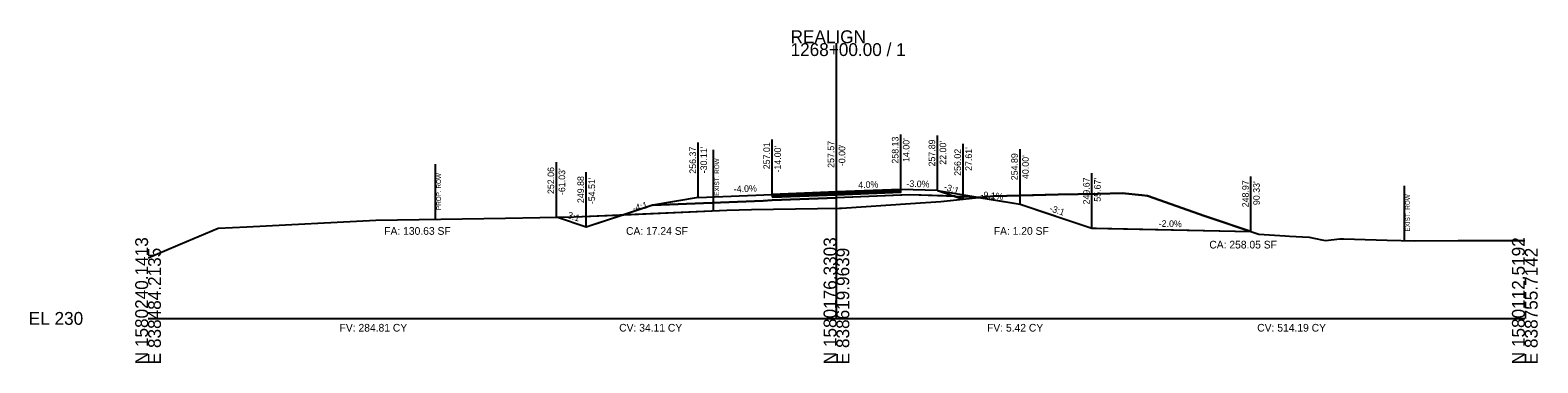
# Model space of a CAD drawing. Extents: x -26 to 6303, y -16 to 9563.
# Drawn here: x 4974.3 to 5302.8, y 990.3 to 1062.8 of the extents above; entities that cross this region are included whole.
import ezdxf

# ---------------------------------------------------------------- set-up
doc = ezdxf.new("R2010")
doc.units = 0
for name, color, linetype in [('ASPHALT_19MM1', 7, 'Continuous'), ('ASPHALT_9_5MM1', 7, 'Continuous'), ('CONST_DCH', 7, 'Continuous'), ('CONST_LV3', 7, 'Continuous'), ('Default', 7, 'Continuous'), ('Draft_XS_Grid', 7, 'Continuous'), ('DTM_TEMP_DROP', 7, 'Continuous'), ('DTM_X_GROUND', 7, 'Continuous'), ('X_TRANS_EOP', 7, 'Continuous'), ('XS_CELL', 7, 'Continuous'), ('XS_M_SHAPES_EARTHWORK', 7, 'Continuous'), ('XS_P_GROUND', 7, 'Continuous'), ('XS_P_ROW', 7, 'Continuous'), ('XS_P_SHOULDER', 7, 'Continuous'), ('XS_P_SUBGRADE_GRANULAR', 7, 'Continuous'), ('XS_P_TX_CLEARZONE', 7, 'Continuous'), ('XS_P_TX_FS_BS', 7, 'Continuous'), ('XS_SHEET_EW_TX_AREA', 7, 'Continuous'), ('XS_SHEET_EW_TX_VOLUME', 7, 'Continuous'), ('XS_X_ROW', 7, 'Continuous')]:
    doc.layers.add(name, color=color, linetype=linetype)

msp = doc.modelspace()

# ---------------------------------------------------------------- linework, layer by layer
at = {"layer": 'ASPHALT_19MM1'}
msp.add_lwpolyline([(5136, 1026.41), (5136, 1026.41), (5136, 1026.41), (5150, 1026.97), (5150, 1026.97), (5164, 1027.53), (5164, 1027.53), (5164, 1027.8), (5150, 1027.24), (5150, 1027.24), (5136, 1026.68), (5136, 1026.68), (5136, 1026.41)], dxfattribs=at)
at = {"layer": 'ASPHALT_9_5MM1'}
msp.add_lwpolyline([(5136, 1026.89), (5136, 1026.89), (5136, 1026.89), (5150, 1027.45), (5150, 1027.45), (5164, 1028.01), (5164, 1028.01), (5164, 1028.13), (5150, 1027.57), (5150, 1027.57), (5136, 1027.01), (5136, 1027.01), (5136, 1026.89)], dxfattribs=at)
at = {"layer": 'CONST_LV3'}
for points in [[(5164, 1028.13), (5150, 1027.57), (5150, 1027.57)], [(5172, 1027.89), (5172, 1027.89), (5164, 1028.13)]]:
    msp.add_lwpolyline(points, dxfattribs=at)
at = {"layer": 'Default'}
msp.add_lwpolyline([(5136, 1026.68), (5136, 1026.68), (5136, 1026.68), (5150, 1027.24), (5150, 1027.24), (5164, 1027.8), (5164, 1027.8), (5164, 1028.01), (5150, 1027.45), (5150, 1027.45), (5136, 1026.89), (5136, 1026.89), (5136, 1026.68)], dxfattribs=at)
at = {"layer": 'DTM_X_GROUND'}
msp.add_lwpolyline([(5000, 1013.26), (5000.15, 1013.27), (5007.03, 1016.21), (5015.31, 1019.69), (5021.55, 1019.94), (5049.6, 1021.43), (5077.89, 1021.84), (5092.88, 1022.13), (5126.09, 1023.58), (5131.49, 1023.77), (5150.65, 1024.01), (5151.08, 1024.04), (5166.12, 1025.02), (5172.77, 1025.5), (5180.93, 1026.37), (5181.41, 1026.4), (5181.61, 1026.45), (5181.81, 1026.46), (5184.28, 1026.66), (5192.95, 1026.86), (5198.29, 1026.99), (5207.05, 1027.18), (5212.28, 1027.29), (5216.56, 1026.86), (5217.8, 1026.72), (5230.33, 1022.3), (5242.07, 1018.39), (5247.79, 1018.02), (5248.76, 1017.96), (5252.99, 1017.7), (5255.78, 1017.15), (5256.56, 1017), (5259.71, 1017.31), (5260.49, 1017.38), (5267.58, 1017.11), (5269.98, 1017.02), (5276.07, 1016.88), (5285.5, 1016.98), (5300, 1017)], dxfattribs=at)
at = {"layer": 'XS_CELL'}
for p, q in [((5150, 1000), (5150, 1060)), ((5000, 1000), (5150, 1000)), ((5150, 1000), (5300, 1000))]:
    msp.add_line(p, q, dxfattribs=at)
at = {"layer": 'XS_M_SHAPES_EARTHWORK'}
for points in [[(5103.65, 1022.6), (5126.09, 1023.58), (5131.49, 1023.77), (5150.65, 1024.01), (5151.08, 1024.04), (5166.12, 1025.02), (5172.77, 1025.5), (5177.61, 1026.02), (5175.73, 1026.65), (5166, 1026.94), (5164, 1026.86), (5150, 1026.3), (5136, 1025.74), (5134, 1025.66), (5109.94, 1024.7)], [(5088.97, 1022.06), (5092.88, 1022.13), (5103.65, 1022.6), (5095.49, 1019.88)]]:
    msp.add_lwpolyline(points, close=True, dxfattribs=at)
at = {"layer": 'XS_P_GROUND'}
for points in [[(5119.89, 1026.37), (5110, 1024.72), (5095.49, 1019.88)], [(5172, 1027.89), (5177.61, 1026.02)], [(5172, 1027.89), (5190, 1024.89), (5205.67, 1019.67)], [(5095.49, 1019.88), (5088.97, 1022.06)], [(5205.67, 1019.67), (5206.67, 1019.65)], [(5206.67, 1019.65), (5240.33, 1018.97)]]:
    msp.add_lwpolyline(points, dxfattribs=at)
at = {"layer": 'XS_P_ROW'}
msp.add_line((5062.62, 1021.62), (5062.62, 1033.62), dxfattribs=at)
at = {"layer": 'XS_P_SHOULDER'}
for points in [[(5119.89, 1026.37), (5136, 1027.01), (5136, 1027.01)], [(5172, 1027.89), (5172, 1027.89), (5164, 1028.13)]]:
    msp.add_lwpolyline(points, dxfattribs=at)
at = {"layer": 'XS_P_SUBGRADE_GRANULAR'}
for points in [[(5109.94, 1024.7), (5134, 1025.66), (5134, 1025.66), (5134, 1025.66), (5136, 1025.74)], [(5136, 1025.74), (5136, 1025.74), (5150, 1026.3)], [(5166, 1026.94), (5150, 1026.3), (5150, 1026.3)], [(5181.17, 1026.36), (5181.17, 1026.36), (5174, 1026.65), (5166, 1026.94), (5166, 1026.94)]]:
    msp.add_lwpolyline(points, dxfattribs=at)
at = {"layer": 'XS_P_TX_CLEARZONE'}
for p, q in [((5119.89, 1026.37), (5119.89, 1038.37)), ((5136, 1027.01), (5136, 1039.01)), ((5150, 1027.57), (5150, 1039.57)), ((5164, 1028.12), (5164, 1040.12)), ((5172, 1027.89), (5172, 1039.89)), ((5177.61, 1026.02), (5177.61, 1038.02)), ((5190, 1024.89), (5190, 1036.89)), ((5088.97, 1022.06), (5088.97, 1034.06)), ((5095.49, 1019.88), (5095.49, 1031.88)), ((5205.67, 1019.67), (5205.67, 1031.67)), ((5240.33, 1018.97), (5240.33, 1030.97))]:
    msp.add_line(p, q, dxfattribs=at)
at = {"layer": 'XS_P_TX_FS_BS'}
for p, q in [((5184.28, 1026.66), (5181.03, 1026.38)), ((5181.03, 1026.38), (5190, 1024.88)), ((5205.67, 1019.67), (5240.33, 1018.97))]:
    msp.add_line(p, q, dxfattribs=at)
for points in [[(5240.33, 1018.97), (5230.33, 1022.3), (5217.8, 1026.72), (5216.56, 1026.86), (5212.28, 1027.29), (5207.05, 1027.18), (5198.29, 1026.99), (5184.28, 1026.66)], [(5190, 1024.88), (5196.52, 1022.71), (5205.67, 1019.67)]]:
    msp.add_lwpolyline(points, dxfattribs=at)
at = {"layer": 'XS_X_ROW'}
for p, q in [((5123.24, 1023.46), (5123.24, 1036.75)), ((5273.76, 1016.93), (5273.76, 1028.93))]:
    msp.add_line(p, q, dxfattribs=at)

# ---------------------------------------------------------------- texts
at = {"layer": 'CONST_DCH'}
for p in [(5171.92, 1027.77), (5189.92, 1024.77)]:
    msp.add_text('X', height=0.24, dxfattribs=at).set_placement(p)
at = {"layer": 'Draft_XS_Grid'}
msp.add_text('-', height=0.0001, dxfattribs=at).set_placement((5000, 1000))
at = {"layer": 'DTM_TEMP_DROP'}
for p in [(5135.92, 1026.89), (5149.92, 1027.45), (5163.92, 1028.01)]:
    msp.add_text('X', height=0.24, dxfattribs=at).set_placement(p)
at = {"layer": 'X_TRANS_EOP'}
for p in [(5177.54, 1025.9), (5088.89, 1021.94)]:
    msp.add_text('X', height=0.24, dxfattribs=at).set_placement(p)
at = {"layer": 'XS_CELL'}
for s, p in [('REALIGN', (5140, 1060)), ('1268+00.00 / 1', (5140, 1057.2)), ('EL 230', (4974, 998.6))]:
    msp.add_text(s, height=2.8, dxfattribs=at).set_placement(p)
for s, p in [('N 1580240.1413', (5000, 990)), ('E 838484.2135', (5002.8, 990)), ('N 1580176.3303', (5150, 990)), ('E 838619.9639', (5152.8, 990)), ('N 1580112.5192', (5300, 990)), ('E 838755.7142', (5302.8, 990))]:
    msp.add_text(s, height=2.8, rotation=90, dxfattribs=at).set_placement(p)
at = {"layer": 'XS_P_GROUND'}
msp.add_text('X', height=0.24, dxfattribs=at).set_placement((5171.92, 1027.77))
at = {"layer": 'XS_P_ROW'}
msp.add_text('PROP. ROW', height=1, rotation=90, dxfattribs=at).set_placement((5063.82, 1023.62))
at = {"layer": 'XS_P_SHOULDER'}
for p in [(5119.81, 1026.25), (5171.92, 1027.77), (5205.59, 1019.55)]:
    msp.add_text('X', height=0.24, dxfattribs=at).set_placement(p)
at = {"layer": 'XS_P_SUBGRADE_GRANULAR'}
for p in [(5177.54, 1025.9), (5095.41, 1019.76), (5240.25, 1018.85)]:
    msp.add_text('X', height=0.24, dxfattribs=at).set_placement(p)
at = {"layer": 'XS_P_TX_CLEARZONE'}
for s, p in [('257.01', (5135.52, 1032.51)), ('257.57', (5149.52, 1032.82)), ('258.13', (5163.52, 1033.74)), ("14.00'", (5165.92, 1034.1)), ('257.89', (5171.52, 1033.12)), ("22.00'", (5173.92, 1033.5)), ('256.37', (5119.41, 1031.54)), ("-30.11'", (5121.81, 1031.63)), ("-14.00'", (5137.92, 1031.8)), ("-0.00'", (5151.92, 1033.18)), ('256.02', (5177.13, 1031.08)), ("27.61'", (5179.53, 1032.15)), ('254.89', (5189.52, 1030.12)), ("40.00'", (5191.92, 1030.39)), ('252.06', (5088.49, 1027.11)), ("-61.03'", (5090.89, 1026.89)), ('249.88', (5095.01, 1025.13)), ("-54.51'", (5097.41, 1024.9)), ('249.67', (5205.19, 1024.84)), ("55.67'", (5207.59, 1025.43)), ('248.97', (5239.85, 1024.22)), ("90.33'", (5242.25, 1024.7))]:
    msp.add_text(s, height=1.44, rotation=90, dxfattribs=at).set_placement(p)
at = {"layer": 'XS_P_TX_FS_BS'}
for s, rotation, p in [('-4.0%', 2.2906, (5127.65, 1027.46)), ('4.0%', 2.2673, (5154.77, 1028.36)), ('-3.0%', 358.2816, (5165.23, 1028.69)), ('-3:1', 341.5651, (5173.28, 1028.1)), ('-4:1', 14.8838, (5105.78, 1023.24)), ('-9.1%', 354.794, (5181.32, 1026.28)), ('3:1', 341.5651, (5091.26, 1021.93)), ('-3:1', 341.5651, (5196.3, 1023.42)), ('-2.0%', 358.8542, (5220.22, 1019.98))]:
    msp.add_text(s, height=1.44, rotation=rotation, dxfattribs=at).set_placement(p)
at = {"layer": 'XS_SHEET_EW_TX_AREA'}
for s, p in [('FA: 130.63 SF', (5051.46, 1018.22)), ('CA: 17.24 SF', (5104.15, 1018.22)), ('FA: 1.20 SF', (5184.28, 1018.22)), ('CA: 258.05 SF', (5231.25, 1015.24))]:
    msp.add_text(s, height=1.68, dxfattribs=at).set_placement(p)
at = {"layer": 'XS_SHEET_EW_TX_VOLUME'}
for s, p in [('FV: 284.81 CY', (5041.73, 997.12)), ('CV: 34.11 CY', (5102.66, 997.12)), ('FV: 5.42 CY', (5182.82, 997.12)), ('CV: 514.19 CY', (5241.69, 997.12))]:
    msp.add_text(s, height=1.68, dxfattribs=at).set_placement(p)
at = {"layer": 'XS_X_ROW'}
for p in [(5124.44, 1026.75), (5274.96, 1018.93)]:
    msp.add_text('EXIST. ROW', height=1, rotation=90, dxfattribs=at).set_placement(p)

doc.saveas('drawing.dxf')
